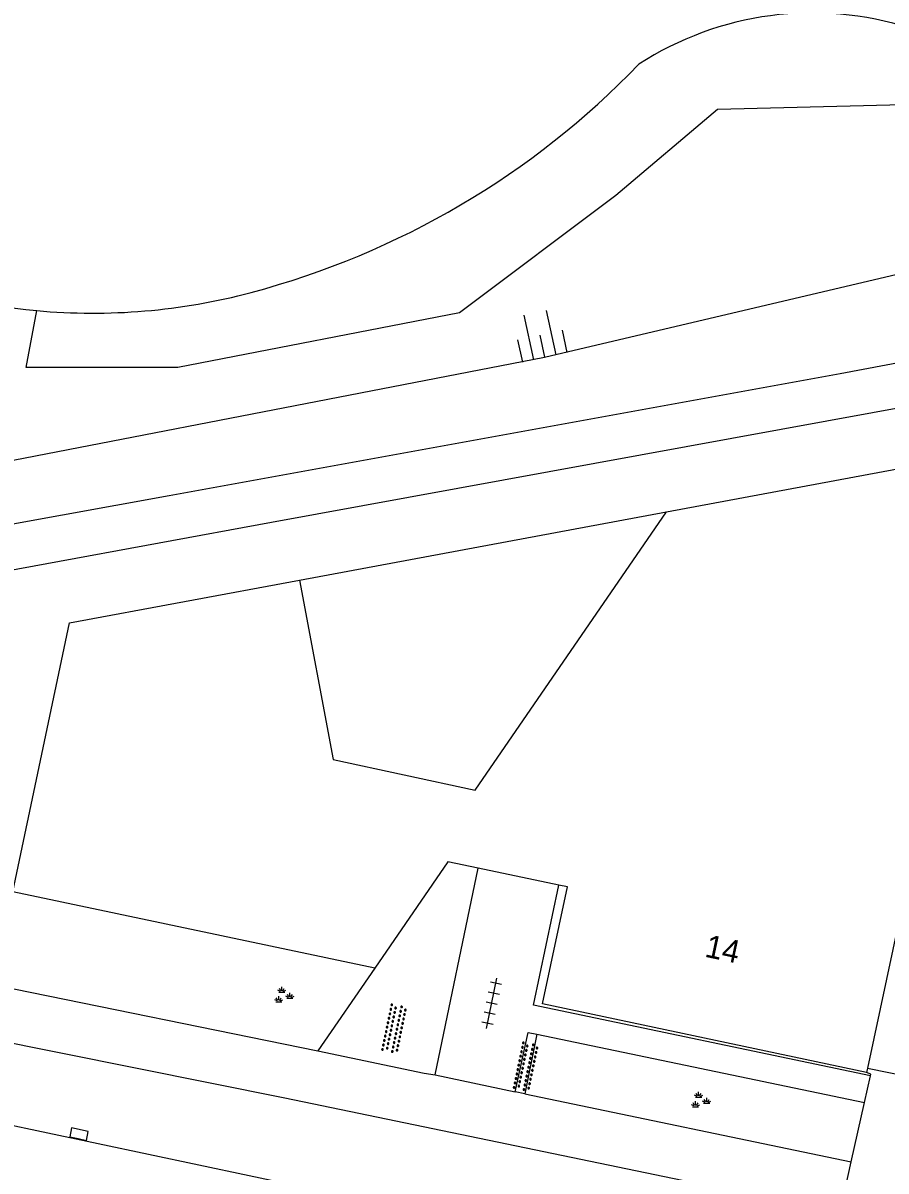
# Model space of a CAD drawing. Extents: x 131000 to 133013, y 393000 to 396501.
# Drawn here: x 131650.8 to 131688.6, y 393635.9 to 393686.3 of the extents above; entities that cross this region are included whole.
import ezdxf

# ---------------------------------------------------------------- set-up
doc = ezdxf.new("R2010")
doc.units = 0
for name, color, linetype in [('gg-afsc-hekwerk', 7, 'Continuous'), ('gg-anno-huisnummerreeks BGT', 7, 'Continuous'), ('gg-bbg-hoofdgebouw', 7, 'Continuous'), ('gg-knt-BGT kruinlijn', 7, 'Continuous'), ('gg-knt-onverhard', 7, 'Continuous'), ('gg-knt-verharding', 7, 'Continuous'), ('gg-kntw-bovenkant insteek waterloop', 7, 'Continuous'), ('gt-grn-groengrens', 7, 'Continuous'), ('gt-symb-groenvak', 7, 'Continuous'), ('gt-symb-kolk', 7, 'Continuous'), ('gt-symb-overige verharding', 7, 'Continuous'), ('gt-symb-talud symbool', 7, 'Continuous'), ('gt-symb-tegel verharding', 7, 'Continuous')]:
    doc.layers.add(name, color=color, linetype=linetype)

# ---------------------------------------------------------------- blocks, each defined once
blk = doc.blocks.new('gt0-GRVAK')
at = {"layer": 'gt-symb-groenvak'}
for p, q in [((-0.11, 0.189), (-0.228, 0.24)), ((-0.182, 0.153), (0.088, 0.153)), ((-0.091, 0.211), (-0.156, 0.322)), ((-0.047, 0.214), (-0.047, 0.393)), ((-0.004, 0.211), (0.061, 0.322)), ((0.015, 0.189), (0.133, 0.24)), ((0.262, -0.052), (0.197, 0.059)), ((0.305, -0.049), (0.305, 0.13)), ((0.349, -0.052), (0.414, 0.059)), ((-0.245, -0.228), (-0.363, -0.177)), ((-0.318, -0.264), (-0.047, -0.264)), ((-0.226, -0.206), (-0.291, -0.095)), ((-0.183, -0.203), (-0.183, -0.024)), ((-0.139, -0.206), (-0.074, -0.095)), ((-0.12, -0.228), (-0.002, -0.177)), ((0.243, -0.074), (0.125, -0.023)), ((0.17, -0.11), (0.441, -0.11)), ((0.368, -0.074), (0.486, -0.023))]:
    blk.add_line(p, q, dxfattribs=at)
blk = doc.blocks.new('gt0-OVH')
at = {"layer": 'gt-symb-overige verharding'}
for points in [[(-0.972, 0.298), (-0.967, 0.308), (-0.965, 0.319), (-0.966, 0.33), (-0.971, 0.34), (-0.978, 0.348), (-0.988, 0.353), (-0.999, 0.355), (-1.01, 0.354), (-1.02, 0.349), (-1.028, 0.342), (-1.033, 0.332), (-1.035, 0.321), (-1.034, 0.31), (-1.029, 0.3), (-1.022, 0.292), (-1.012, 0.287), (-1.001, 0.285), (-0.99, 0.286), (-0.98, 0.291)], [(-0.872, 0.106), (-0.867, 0.116), (-0.865, 0.126), (-0.866, 0.137), (-0.871, 0.147), (-0.878, 0.156), (-0.888, 0.161), (-0.899, 0.163), (-0.91, 0.162), (-0.92, 0.157), (-0.928, 0.15), (-0.933, 0.14), (-0.935, 0.129), (-0.934, 0.118), (-0.929, 0.108), (-0.922, 0.1), (-0.912, 0.095), (-0.901, 0.092), (-0.89, 0.094), (-0.88, 0.098)], [(-0.772, 0.298), (-0.767, 0.308), (-0.765, 0.319), (-0.766, 0.33), (-0.771, 0.34), (-0.778, 0.348), (-0.788, 0.353), (-0.799, 0.355), (-0.81, 0.354), (-0.82, 0.349), (-0.828, 0.342), (-0.833, 0.332), (-0.835, 0.321), (-0.834, 0.31), (-0.829, 0.3), (-0.822, 0.292), (-0.812, 0.287), (-0.801, 0.285), (-0.79, 0.286), (-0.78, 0.291)], [(-0.672, 0.106), (-0.667, 0.116), (-0.665, 0.126), (-0.666, 0.137), (-0.671, 0.147), (-0.678, 0.156), (-0.688, 0.161), (-0.699, 0.163), (-0.71, 0.162), (-0.72, 0.157), (-0.728, 0.15), (-0.733, 0.14), (-0.735, 0.129), (-0.734, 0.118), (-0.729, 0.108), (-0.722, 0.1), (-0.712, 0.095), (-0.701, 0.092), (-0.69, 0.094), (-0.68, 0.098)], [(-0.572, 0.298), (-0.567, 0.308), (-0.565, 0.319), (-0.566, 0.33), (-0.571, 0.34), (-0.578, 0.348), (-0.588, 0.353), (-0.599, 0.355), (-0.61, 0.354), (-0.62, 0.349), (-0.628, 0.342), (-0.633, 0.332), (-0.635, 0.321), (-0.634, 0.31), (-0.629, 0.3), (-0.622, 0.292), (-0.612, 0.287), (-0.601, 0.285), (-0.59, 0.286), (-0.58, 0.291)], [(-0.472, 0.106), (-0.467, 0.116), (-0.465, 0.126), (-0.466, 0.137), (-0.471, 0.147), (-0.478, 0.156), (-0.488, 0.161), (-0.499, 0.163), (-0.51, 0.162), (-0.52, 0.157), (-0.528, 0.15), (-0.533, 0.14), (-0.535, 0.129), (-0.534, 0.118), (-0.529, 0.108), (-0.522, 0.1), (-0.512, 0.095), (-0.501, 0.092), (-0.49, 0.094), (-0.48, 0.098)], [(-0.372, 0.298), (-0.367, 0.308), (-0.365, 0.319), (-0.366, 0.33), (-0.371, 0.34), (-0.378, 0.348), (-0.388, 0.353), (-0.399, 0.355), (-0.41, 0.354), (-0.42, 0.349), (-0.428, 0.342), (-0.433, 0.332), (-0.435, 0.321), (-0.434, 0.31), (-0.429, 0.3), (-0.422, 0.292), (-0.412, 0.287), (-0.401, 0.285), (-0.39, 0.286), (-0.38, 0.291)], [(-0.272, 0.106), (-0.267, 0.116), (-0.265, 0.126), (-0.266, 0.137), (-0.271, 0.147), (-0.278, 0.156), (-0.288, 0.161), (-0.299, 0.163), (-0.31, 0.162), (-0.32, 0.157), (-0.328, 0.15), (-0.333, 0.14), (-0.335, 0.129), (-0.334, 0.118), (-0.329, 0.108), (-0.322, 0.1), (-0.312, 0.095), (-0.301, 0.092), (-0.29, 0.094), (-0.28, 0.098)], [(-0.172, 0.298), (-0.167, 0.308), (-0.165, 0.319), (-0.166, 0.33), (-0.171, 0.34), (-0.178, 0.348), (-0.188, 0.353), (-0.199, 0.355), (-0.21, 0.354), (-0.22, 0.349), (-0.228, 0.342), (-0.233, 0.332), (-0.235, 0.321), (-0.234, 0.31), (-0.229, 0.3), (-0.222, 0.292), (-0.212, 0.287), (-0.201, 0.285), (-0.19, 0.286), (-0.18, 0.291)], [(-0.072, 0.106), (-0.067, 0.116), (-0.065, 0.126), (-0.066, 0.137), (-0.071, 0.147), (-0.078, 0.156), (-0.088, 0.161), (-0.099, 0.163), (-0.11, 0.162), (-0.12, 0.157), (-0.128, 0.15), (-0.133, 0.14), (-0.135, 0.129), (-0.134, 0.118), (-0.129, 0.108), (-0.122, 0.1), (-0.112, 0.095), (-0.101, 0.092), (-0.09, 0.094), (-0.08, 0.098)], [(0.028, 0.298), (0.033, 0.308), (0.035, 0.319), (0.034, 0.33), (0.029, 0.34), (0.022, 0.348), (0.012, 0.353), (0.001, 0.355), (-0.01, 0.354), (-0.02, 0.349), (-0.028, 0.342), (-0.033, 0.332), (-0.035, 0.321), (-0.034, 0.31), (-0.029, 0.3), (-0.022, 0.292), (-0.012, 0.287), (-0.001, 0.285), (0.01, 0.286), (0.02, 0.291)], [(0.128, 0.106), (0.133, 0.116), (0.135, 0.126), (0.134, 0.137), (0.129, 0.147), (0.122, 0.156), (0.112, 0.161), (0.101, 0.163), (0.09, 0.162), (0.08, 0.157), (0.072, 0.15), (0.067, 0.14), (0.065, 0.129), (0.066, 0.118), (0.071, 0.108), (0.078, 0.1), (0.088, 0.095), (0.099, 0.092), (0.11, 0.094), (0.12, 0.098)], [(0.228, 0.298), (0.233, 0.308), (0.235, 0.319), (0.234, 0.33), (0.229, 0.34), (0.222, 0.348), (0.212, 0.353), (0.201, 0.355), (0.19, 0.354), (0.18, 0.349), (0.172, 0.342), (0.167, 0.332), (0.165, 0.321), (0.166, 0.31), (0.171, 0.3), (0.178, 0.292), (0.188, 0.287), (0.199, 0.285), (0.21, 0.286), (0.22, 0.291)], [(0.328, 0.106), (0.333, 0.116), (0.335, 0.126), (0.334, 0.137), (0.329, 0.147), (0.322, 0.156), (0.312, 0.161), (0.301, 0.163), (0.29, 0.162), (0.28, 0.157), (0.272, 0.15), (0.267, 0.14), (0.265, 0.129), (0.266, 0.118), (0.271, 0.108), (0.278, 0.1), (0.288, 0.095), (0.299, 0.092), (0.31, 0.094), (0.32, 0.098)], [(0.428, 0.298), (0.433, 0.308), (0.435, 0.319), (0.434, 0.33), (0.429, 0.34), (0.422, 0.348), (0.412, 0.353), (0.401, 0.355), (0.39, 0.354), (0.38, 0.349), (0.372, 0.342), (0.367, 0.332), (0.365, 0.321), (0.366, 0.31), (0.371, 0.3), (0.378, 0.292), (0.388, 0.287), (0.399, 0.285), (0.41, 0.286), (0.42, 0.291)], [(0.528, 0.106), (0.533, 0.116), (0.535, 0.126), (0.534, 0.137), (0.529, 0.147), (0.522, 0.156), (0.512, 0.161), (0.501, 0.163), (0.49, 0.162), (0.48, 0.157), (0.472, 0.15), (0.467, 0.14), (0.465, 0.129), (0.466, 0.118), (0.471, 0.108), (0.478, 0.1), (0.488, 0.095), (0.499, 0.092), (0.51, 0.094), (0.52, 0.098)], [(0.628, 0.298), (0.633, 0.308), (0.635, 0.319), (0.634, 0.33), (0.629, 0.34), (0.622, 0.348), (0.612, 0.353), (0.601, 0.355), (0.59, 0.354), (0.58, 0.349), (0.572, 0.342), (0.567, 0.332), (0.565, 0.321), (0.566, 0.31), (0.571, 0.3), (0.578, 0.292), (0.588, 0.287), (0.599, 0.285), (0.61, 0.286), (0.62, 0.291)], [(0.728, 0.106), (0.733, 0.116), (0.735, 0.126), (0.734, 0.137), (0.729, 0.147), (0.722, 0.156), (0.712, 0.161), (0.701, 0.163), (0.69, 0.162), (0.68, 0.157), (0.672, 0.15), (0.667, 0.14), (0.665, 0.129), (0.666, 0.118), (0.671, 0.108), (0.678, 0.1), (0.688, 0.095), (0.699, 0.092), (0.71, 0.094), (0.72, 0.098)], [(0.828, 0.298), (0.833, 0.308), (0.835, 0.319), (0.834, 0.33), (0.829, 0.34), (0.822, 0.348), (0.812, 0.353), (0.801, 0.355), (0.79, 0.354), (0.78, 0.349), (0.772, 0.342), (0.767, 0.332), (0.765, 0.321), (0.766, 0.31), (0.771, 0.3), (0.778, 0.292), (0.788, 0.287), (0.799, 0.285), (0.81, 0.286), (0.82, 0.291)], [(0.928, 0.106), (0.933, 0.116), (0.935, 0.126), (0.934, 0.137), (0.929, 0.147), (0.922, 0.156), (0.912, 0.161), (0.901, 0.163), (0.89, 0.162), (0.88, 0.157), (0.872, 0.15), (0.867, 0.14), (0.865, 0.129), (0.866, 0.118), (0.871, 0.108), (0.878, 0.1), (0.888, 0.095), (0.899, 0.092), (0.91, 0.094), (0.92, 0.098)], [(1.028, 0.298), (1.033, 0.308), (1.035, 0.319), (1.034, 0.33), (1.029, 0.34), (1.022, 0.348), (1.012, 0.353), (1.001, 0.355), (0.99, 0.354), (0.98, 0.349), (0.972, 0.342), (0.967, 0.332), (0.965, 0.321), (0.966, 0.31), (0.971, 0.3), (0.978, 0.292), (0.988, 0.287), (0.999, 0.285), (1.01, 0.286), (1.02, 0.291)], [(-0.972, -0.142), (-0.967, -0.132), (-0.965, -0.121), (-0.966, -0.11), (-0.971, -0.1), (-0.978, -0.092), (-0.988, -0.087), (-0.999, -0.085), (-1.01, -0.086), (-1.02, -0.091), (-1.028, -0.098), (-1.033, -0.108), (-1.035, -0.119), (-1.034, -0.13), (-1.029, -0.14), (-1.022, -0.148), (-1.012, -0.153), (-1.001, -0.155), (-0.99, -0.154), (-0.98, -0.149)], [(-0.872, -0.334), (-0.867, -0.324), (-0.865, -0.314), (-0.866, -0.303), (-0.871, -0.293), (-0.878, -0.284), (-0.888, -0.279), (-0.899, -0.277), (-0.91, -0.278), (-0.92, -0.283), (-0.928, -0.29), (-0.933, -0.3), (-0.935, -0.311), (-0.934, -0.322), (-0.929, -0.332), (-0.922, -0.34), (-0.912, -0.345), (-0.901, -0.348), (-0.89, -0.346), (-0.88, -0.342)], [(-0.772, -0.142), (-0.767, -0.132), (-0.765, -0.121), (-0.766, -0.11), (-0.771, -0.1), (-0.778, -0.092), (-0.788, -0.087), (-0.799, -0.085), (-0.81, -0.086), (-0.82, -0.091), (-0.828, -0.098), (-0.833, -0.108), (-0.835, -0.119), (-0.834, -0.13), (-0.829, -0.14), (-0.822, -0.148), (-0.812, -0.153), (-0.801, -0.155), (-0.79, -0.154), (-0.78, -0.149)], [(-0.672, -0.334), (-0.667, -0.324), (-0.665, -0.314), (-0.666, -0.303), (-0.671, -0.293), (-0.678, -0.284), (-0.688, -0.279), (-0.699, -0.277), (-0.71, -0.278), (-0.72, -0.283), (-0.728, -0.29), (-0.733, -0.3), (-0.735, -0.311), (-0.734, -0.322), (-0.729, -0.332), (-0.722, -0.34), (-0.712, -0.345), (-0.701, -0.348), (-0.69, -0.346), (-0.68, -0.342)], [(-0.572, -0.142), (-0.567, -0.132), (-0.565, -0.121), (-0.566, -0.11), (-0.571, -0.1), (-0.578, -0.092), (-0.588, -0.087), (-0.599, -0.085), (-0.61, -0.086), (-0.62, -0.091), (-0.628, -0.098), (-0.633, -0.108), (-0.635, -0.119), (-0.634, -0.13), (-0.629, -0.14), (-0.622, -0.148), (-0.612, -0.153), (-0.601, -0.155), (-0.59, -0.154), (-0.58, -0.149)], [(-0.472, -0.334), (-0.467, -0.324), (-0.465, -0.314), (-0.466, -0.303), (-0.471, -0.293), (-0.478, -0.284), (-0.488, -0.279), (-0.499, -0.277), (-0.51, -0.278), (-0.52, -0.283), (-0.528, -0.29), (-0.533, -0.3), (-0.535, -0.311), (-0.534, -0.322), (-0.529, -0.332), (-0.522, -0.34), (-0.512, -0.345), (-0.501, -0.348), (-0.49, -0.346), (-0.48, -0.342)], [(-0.372, -0.142), (-0.367, -0.132), (-0.365, -0.121), (-0.366, -0.11), (-0.371, -0.1), (-0.378, -0.092), (-0.388, -0.087), (-0.399, -0.085), (-0.41, -0.086), (-0.42, -0.091), (-0.428, -0.098), (-0.433, -0.108), (-0.435, -0.119), (-0.434, -0.13), (-0.429, -0.14), (-0.422, -0.148), (-0.412, -0.153), (-0.401, -0.155), (-0.39, -0.154), (-0.38, -0.149)], [(-0.272, -0.334), (-0.267, -0.324), (-0.265, -0.314), (-0.266, -0.303), (-0.271, -0.293), (-0.278, -0.284), (-0.288, -0.279), (-0.299, -0.277), (-0.31, -0.278), (-0.32, -0.283), (-0.328, -0.29), (-0.333, -0.3), (-0.335, -0.311), (-0.334, -0.322), (-0.329, -0.332), (-0.322, -0.34), (-0.312, -0.345), (-0.301, -0.348), (-0.29, -0.346), (-0.28, -0.342)], [(-0.172, -0.142), (-0.167, -0.132), (-0.165, -0.121), (-0.166, -0.11), (-0.171, -0.1), (-0.178, -0.092), (-0.188, -0.087), (-0.199, -0.085), (-0.21, -0.086), (-0.22, -0.091), (-0.228, -0.098), (-0.233, -0.108), (-0.235, -0.119), (-0.234, -0.13), (-0.229, -0.14), (-0.222, -0.148), (-0.212, -0.153), (-0.201, -0.155), (-0.19, -0.154), (-0.18, -0.149)], [(-0.072, -0.334), (-0.067, -0.324), (-0.065, -0.314), (-0.066, -0.303), (-0.071, -0.293), (-0.078, -0.284), (-0.088, -0.279), (-0.099, -0.277), (-0.11, -0.278), (-0.12, -0.283), (-0.128, -0.29), (-0.133, -0.3), (-0.135, -0.311), (-0.134, -0.322), (-0.129, -0.332), (-0.122, -0.34), (-0.112, -0.345), (-0.101, -0.348), (-0.09, -0.346), (-0.08, -0.342)], [(0.028, -0.142), (0.033, -0.132), (0.035, -0.121), (0.034, -0.11), (0.029, -0.1), (0.022, -0.092), (0.012, -0.087), (0.001, -0.085), (-0.01, -0.086), (-0.02, -0.091), (-0.028, -0.098), (-0.033, -0.108), (-0.035, -0.119), (-0.034, -0.13), (-0.029, -0.14), (-0.022, -0.148), (-0.012, -0.153), (-0.001, -0.155), (0.01, -0.154), (0.02, -0.149)], [(0.128, -0.334), (0.133, -0.324), (0.135, -0.314), (0.134, -0.303), (0.129, -0.293), (0.122, -0.284), (0.112, -0.279), (0.101, -0.277), (0.09, -0.278), (0.08, -0.283), (0.072, -0.29), (0.067, -0.3), (0.065, -0.311), (0.066, -0.322), (0.071, -0.332), (0.078, -0.34), (0.088, -0.345), (0.099, -0.348), (0.11, -0.346), (0.12, -0.342)], [(0.228, -0.142), (0.233, -0.132), (0.235, -0.121), (0.234, -0.11), (0.229, -0.1), (0.222, -0.092), (0.212, -0.087), (0.201, -0.085), (0.19, -0.086), (0.18, -0.091), (0.172, -0.098), (0.167, -0.108), (0.165, -0.119), (0.166, -0.13), (0.171, -0.14), (0.178, -0.148), (0.188, -0.153), (0.199, -0.155), (0.21, -0.154), (0.22, -0.149)], [(0.328, -0.334), (0.333, -0.324), (0.335, -0.314), (0.334, -0.303), (0.329, -0.293), (0.322, -0.284), (0.312, -0.279), (0.301, -0.277), (0.29, -0.278), (0.28, -0.283), (0.272, -0.29), (0.267, -0.3), (0.265, -0.311), (0.266, -0.322), (0.271, -0.332), (0.278, -0.34), (0.288, -0.345), (0.299, -0.348), (0.31, -0.346), (0.32, -0.342)], [(0.428, -0.142), (0.433, -0.132), (0.435, -0.121), (0.434, -0.11), (0.429, -0.1), (0.422, -0.092), (0.412, -0.087), (0.401, -0.085), (0.39, -0.086), (0.38, -0.091), (0.372, -0.098), (0.367, -0.108), (0.365, -0.119), (0.366, -0.13), (0.371, -0.14), (0.378, -0.148), (0.388, -0.153), (0.399, -0.155), (0.41, -0.154), (0.42, -0.149)], [(0.528, -0.334), (0.533, -0.324), (0.535, -0.314), (0.534, -0.303), (0.529, -0.293), (0.522, -0.284), (0.512, -0.279), (0.501, -0.277), (0.49, -0.278), (0.48, -0.283), (0.472, -0.29), (0.467, -0.3), (0.465, -0.311), (0.466, -0.322), (0.471, -0.332), (0.478, -0.34), (0.488, -0.345), (0.499, -0.348), (0.51, -0.346), (0.52, -0.342)], [(0.628, -0.142), (0.633, -0.132), (0.635, -0.121), (0.634, -0.11), (0.629, -0.1), (0.622, -0.092), (0.612, -0.087), (0.601, -0.085), (0.59, -0.086), (0.58, -0.091), (0.572, -0.098), (0.567, -0.108), (0.565, -0.119), (0.566, -0.13), (0.571, -0.14), (0.578, -0.148), (0.588, -0.153), (0.599, -0.155), (0.61, -0.154), (0.62, -0.149)], [(0.728, -0.334), (0.733, -0.324), (0.735, -0.314), (0.734, -0.303), (0.729, -0.293), (0.722, -0.284), (0.712, -0.279), (0.701, -0.277), (0.69, -0.278), (0.68, -0.283), (0.672, -0.29), (0.667, -0.3), (0.665, -0.311), (0.666, -0.322), (0.671, -0.332), (0.678, -0.34), (0.688, -0.345), (0.699, -0.348), (0.71, -0.346), (0.72, -0.342)], [(0.828, -0.142), (0.833, -0.132), (0.835, -0.121), (0.834, -0.11), (0.829, -0.1), (0.822, -0.092), (0.812, -0.087), (0.801, -0.085), (0.79, -0.086), (0.78, -0.091), (0.772, -0.098), (0.767, -0.108), (0.765, -0.119), (0.766, -0.13), (0.771, -0.14), (0.778, -0.148), (0.788, -0.153), (0.799, -0.155), (0.81, -0.154), (0.82, -0.149)], [(0.928, -0.334), (0.933, -0.324), (0.935, -0.314), (0.934, -0.303), (0.929, -0.293), (0.922, -0.284), (0.912, -0.279), (0.901, -0.277), (0.89, -0.278), (0.88, -0.283), (0.872, -0.29), (0.867, -0.3), (0.865, -0.311), (0.866, -0.322), (0.871, -0.332), (0.878, -0.34), (0.888, -0.345), (0.899, -0.348), (0.91, -0.346), (0.92, -0.342)], [(1.028, -0.142), (1.033, -0.132), (1.035, -0.121), (1.034, -0.11), (1.029, -0.1), (1.022, -0.092), (1.012, -0.087), (1.001, -0.085), (0.99, -0.086), (0.98, -0.091), (0.972, -0.098), (0.967, -0.108), (0.965, -0.119), (0.966, -0.13), (0.971, -0.14), (0.978, -0.148), (0.988, -0.153), (0.999, -0.155), (1.01, -0.154), (1.02, -0.149)]]:
    blk.add_lwpolyline(points, close=True, dxfattribs=at)
blk = doc.blocks.new('gt0-TEG1')
at = {"layer": 'gt-symb-tegel verharding'}
for p, q in [((-1.125, 0), (1.125, 0)), ((-0.9, -0.25), (-0.9, 0.25)), ((-0.45, -0.25), (-0.45, 0.25)), ((0, -0.25), (0, 0.25)), ((0.45, -0.25), (0.45, 0.25)), ((0.9, -0.25), (0.9, 0.25))]:
    blk.add_line(p, q, dxfattribs=at)
blk = doc.blocks.new('gt0-TALUD_1')
at = {"layer": 'gt-symb-talud symbool'}
for p, q in [((-1, -1), (-1, 0)), ((-0.5, -2), (-0.5, 0)), ((0, -1), (0, 0)), ((0.5, -2), (0.5, 0)), ((1, -1), (1, 0))]:
    blk.add_line(p, q, dxfattribs=at)
blk = doc.blocks.new('gt0-KOLK')
at = {"layer": 'gt-symb-kolk'}
blk.add_lwpolyline([(0, 0), (0.375, 0), (0.375, 0.4), (-0.375, 0.4), (-0.375, 0), (0, 0)], dxfattribs=at)

msp = doc.modelspace()

# ---------------------------------------------------------------- linework, layer by layer
at = {"layer": 'gg-afsc-hekwerk'}
for p, q in [((131662.913, 393661.862), (131679.016, 393664.862)), ((131687.837, 393640.428), (131692.727, 393639.41))]:
    msp.add_line(p, q, dxfattribs=at)
at = {"layer": 'gg-bbg-hoofdgebouw'}
for p, q in [((131679.016, 393664.862), (131693.604, 393667.579)), ((131693.604, 393667.579), (131687.837, 393640.428)), ((131674.292, 393648.462), (131670.749, 393649.206)), ((131687.837, 393640.428), (131687.795, 393640.232))]:
    msp.add_line(p, q, dxfattribs=at)
for points in [[(131662.913, 393661.862), (131664.38, 393653.983), (131670.625, 393652.642), (131679.016, 393664.862)], [(131666.207, 393644.817), (131650.329, 393648.169), (131652.82, 393659.982), (131662.913, 393661.862)], [(131670.749, 393649.206), (131669.411, 393649.487), (131666.207, 393644.817)], [(131687.795, 393640.232), (131673.577, 393643.255), (131674.664, 393648.384), (131674.292, 393648.462)]]:
    msp.add_lwpolyline(points, dxfattribs=at)
at = {"layer": 'gg-knt-BGT kruinlijn'}
msp.add_lwpolyline([(131641.803, 393665.476), (131673.667, 393671.647), (131693.365, 393676.297), (131705.856, 393677.996), (131720.657, 393682.56)], dxfattribs=at)
at = {"layer": 'gg-knt-onverhard'}
for p, q in [((131603.859, 393653.419), (131663.713, 393641.183)), ((131672.793, 393639.296), (131687.125, 393636.313))]:
    msp.add_line(p, q, dxfattribs=at)
for points in [[(131711.011, 393675.524), (131686.643, 393670.924), (131657.19, 393665.559), (131626.422, 393659.99), (131597.72, 393654.402)], [(131716.45, 393674.44), (131690.067, 393669.582), (131661.686, 393664.394), (131632.084, 393658.951), (131603.859, 393653.419)], [(131632.294, 393641.736), (131632.833, 393645.043), (131662.268, 393639.122), (131686.628, 393634.076)], [(131663.713, 393641.183), (131668.382, 393640.214), (131668.859, 393640.131)]]:
    msp.add_lwpolyline(points, dxfattribs=at)
at = {"layer": 'gg-knt-verharding'}
for p, q in [((131668.859, 393640.131), (131670.749, 393649.206)), ((131666.207, 393644.817), (131663.713, 393641.183)), ((131673.331, 393641.918), (131672.793, 393639.296)), ((131673.331, 393641.918), (131687.708, 393638.926)), ((131632.294, 393641.736), (131680.286, 393631.57)), ((131668.859, 393640.131), (131672.375, 393639.383)), ((131687.708, 393638.926), (131687.966, 393640.088)), ((131672.793, 393639.296), (131672.375, 393639.383)), ((131687.125, 393636.313), (131687.708, 393638.926)), ((131686.628, 393634.076), (131687.125, 393636.313))]:
    msp.add_line(p, q, dxfattribs=at)
for points in [[(131687.966, 393640.088), (131673.181, 393643.197), (131674.292, 393648.462)], [(131672.375, 393639.383), (131672.938, 393642), (131673.331, 393641.918)], [(131687.966, 393640.088), (131687.983, 393640.162), (131687.795, 393640.232)]]:
    msp.add_lwpolyline(points, dxfattribs=at)
at = {"layer": 'gg-kntw-bovenkant insteek waterloop'}
for centre, radius, start, end in [((131685.426, 393672.759), 14.015, 72.2387, 122.9551), ((131651.347, 393709.976), 36.714, 284.8909, 316.1014), ((131653.837, 393700.582), 26.995, 232.4161, 264.7676), ((131653.841, 393700.574), 26.987, 264.7573, 284.9041)]:
    msp.add_arc(centre, radius, start, end, dxfattribs=at)
at = {"layer": 'gt-grn-groengrens'}
msp.add_lwpolyline([(131747.126, 393628.699), (131746.141, 393634.128), (131741.674, 393634.128), (131736.868, 393636.874), (131734.808, 393640.65), (131732.405, 393647.859), (131732.405, 393657.128), (131735.838, 393675.323), (131731.032, 393682.189), (131723.823, 393683.905), (131707.688, 393682.532), (131694.643, 393682.875), (131681.255, 393682.532), (131676.792, 393678.756), (131669.926, 393673.606), (131657.567, 393671.203), (131650.907, 393671.203), (131651.375, 393673.7)], dxfattribs=at)

# ---------------------------------------------------------------- block references
at = {"layer": 'gt-symb-groenvak'}
for p in [(131662.181, 393643.61), (131680.474, 393638.995)]:
    msp.add_blockref('gt0-GRVAK', p, dxfattribs=at)
at = {"layer": 'gt-symb-kolk', "rotation": -11.882758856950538}
msp.add_blockref('gt0-KOLK', (131653.19, 393637.333), dxfattribs=at)
at = {"layer": 'gt-symb-overige verharding'}
for p, rotation in [((131667.066, 393642.162), 78.22937399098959), ((131672.843, 393640.494), 78.22937399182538)]:
    msp.add_blockref('gt0-OVH', p, dxfattribs=dict(at, rotation=rotation))
at = {"layer": 'gt-symb-talud symbool', "xscale": 0.9997364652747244, "yscale": 0.9997364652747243, "rotation": -167.75714042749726}
msp.add_blockref('gt0-TALUD_1', (131673.667, 393671.647), dxfattribs=at)
at = {"layer": 'gt-symb-tegel verharding', "rotation": 78.11724114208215}
msp.add_blockref('gt0-TEG1', (131671.344, 393643.273), dxfattribs=at)

# ---------------------------------------------------------------- texts
at = {"layer": 'gg-anno-huisnummerreeks BGT'}
msp.add_text('14', height=1, rotation=348, dxfattribs=at).set_placement((131680.654, 393645.329))

doc.saveas('drawing.dxf')
